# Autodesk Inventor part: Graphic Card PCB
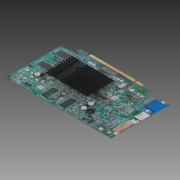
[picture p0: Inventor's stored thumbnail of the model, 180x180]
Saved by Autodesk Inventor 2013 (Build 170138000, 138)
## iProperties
Company: Autodesk Inc.
Created: 2005-12
Part Number: Graphic Card PCB
Document SubType Name: Modeling
Designer: Autodesk Inc.
Density: 1 g/cm^3
Mass: 16.0813 g
Surface Area: 327.607 cm^2
Volume: 16.0813 cm^3
Material: Allgemein
Title: Personal Computer
Author: Autodesk Inc.
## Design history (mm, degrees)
sketch "Sketch1"
  geometry: L1 (0, 84)-(0, -84) reference; L2 (-36, 0)-(216, 0) reference; L3 (0, 60)-(180, 60); L4 (180, 60)-(180, -60); L5 (180, -60)-(0, -60); L6 (0, -60)-(0, 60)
  constraints: 8 end point, 2 parallel, 1 horizontal, 1 perpendicular, 1 point on line, 1 other
  dimensions: "d0" = 180 distance of L4.end L5.end; "d1" = 120 distance of L3.end L4.end
extrude "Extrusion1" new body sketch "Sketch1" distance "d2" = 1; taper "d3" = 0 deg
sketch "Sketch4"
  geometry: L1 (-165.5, 50.52)-(0, 50.52); L2 (0, 50.52)-(0, -50.52); L3 (0, -50.52)-(-165.5, -50.52); L4 (-165.5, -50.52)-(-165.5, 50.52); L5 (0, -60)-(0, 60) reference; 2 further points; 1 other entity
  constraints: 2 midpoint, 2 other
  dimensions: "d9" = 165.5 distance of L1.start L1.end
feature "Decal2" sketch "Sketch4"
sketch "Sketch3"
  geometry: L1 (0, 50.153)-(168, 50.153); L2 (168, 50.153)-(168, -50.153); L3 (168, -50.153)-(0, -50.153); L4 (0, -50.153)-(0, 50.153); 2 further points; 1 other entity
  constraints: 1 midpoint, 2 other
  dimensions: "d10" = 168 distance of L1.start L1.end
feature "Decal3" sketch "Sketch3"
sketch "Sketch5"
  geometry: L1 (0, 60)-(180, 60) reference; L2 (0, -60)-(0, 60) reference; L3 (180, -60)-(0, -60) reference; L4 (0, 38.252)-(25.691, 38.252); L5 (25.691, 38.252)-(25.691, 43.171); L6 (25.691, 43.171)-(19.893, 43.171); L7 (19.893, 43.171)-(19.893, 46.246); L8 (19.893, 46.246)-(21.386, 48.617); L9 (21.386, 48.617)-(33.146, 48.617); L10 (33.146, 48.617)-(33.146, 42.556); L11 (33.146, 42.556)-(35.792, 42.556); L12 (35.792, 42.556)-(35.792, 60); L13 (120.792, 60)-(124.702, 60); L14 (124.702, 60)-(124.702, 40.037); L15 (124.702, 40.037)-(120.792, 40.037); L16 (120.792, 40.037)-(120.792, 60); L17 (35.792, 50.095)-(120.792, 50.018); L18 (107.736, 50.03)-(109.854, 50.03); L19 (109.854, 50.03)-(109.854, 43.66); L20 (109.854, 43.66)-(107.736, 43.66); L21 (107.736, 43.66)-(107.736, 50.03); 2 further points
  constraints: 36 end point, 10 parallel, 5 point on line, 4 perpendicular, 3 midpoint, 2 horizontal, 2 horizontal alignment, 4 other
  dimensions: "d14" = 85 distance between parallel lines of L16 L12
extrude "Extrusion2" cut sketch "Sketch5" stored distance "d11" = 1; taper "d12" = 0 deg
sketch "Sketch6"
  geometry: L1 (124.702, 60)-(124.702, 40.037) reference; L2 (0, -60)-(0, 38.252) reference; L3 (180, -60)-(0, -60) reference; L4 (180, 60)-(180, -60) reference; L5 (124.702, 60)-(180, 60) reference; L6 (124.702, 46.811)-(132.478, 46.811); L7 (132.478, 46.811)-(132.478, 38.248); L8 (168, -50)-(0, -50); L9 (-36, 0)-(216, 0) reference; L10 (168, 43)-(168, -50); L11 (132.478, 38.248)-(150.959, 38.248); L12 (150.959, 38.248)-(150.959, 43); L13 (150.959, 43)-(168, 43)
  constraints: 14 end point, 4 perpendicular, 3 parallel, 2 point on line
  dimensions: "d16" = 93 distance of L10.start L8.start; "d17" = 10 distance between parallel lines of L3 L8; "d18" = 168 distance between parallel lines of L2 L10
extrude "Extrusion3" cut sketch "Sketch6" stored distance "d19" = 1; taper "d20" = 0 deg
body "Solid1"
node "Image3"
node "Image4"
